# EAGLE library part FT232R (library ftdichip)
Source: http://www.ftdichip.com/Documents/DataSheets/DS_FT232R_v104.pdf
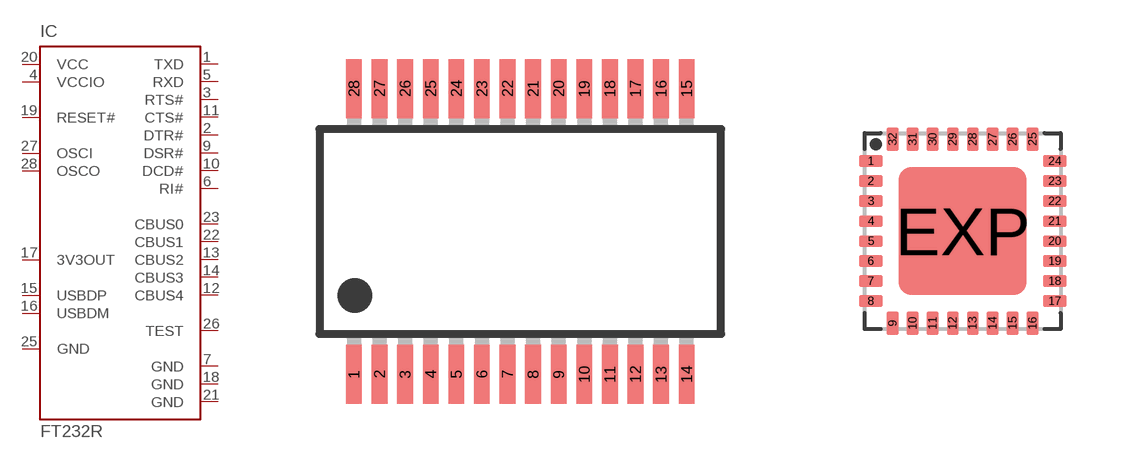
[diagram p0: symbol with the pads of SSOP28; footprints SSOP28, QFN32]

Designator prefix IC

## FT232RL  [SSOP28]
1  TXD  in
2  DTR#  in
3  RTS#  in
4  VCCIO  in
5  RXD  in
6  RI#  in
7  GND  in
9  DSR#  in
10  DCD#  in
11  CTS#  in
12  CBUS4  in
13  CBUS2  in
14  CBUS3  in
15  USBDP  in
16  USBDM  in
17  3V3OUT  in
18  GND  in
19  RESET#  in
20  VCC  in
21  GND  in
22  CBUS1  in
23  CBUS0  in
25  GND  in
26  TEST  in
27  OSCI  in
28  OSCO  in

## FT232RQ  [QFN32]
1  VCCIO  in
2  RXD  in
3  RI#  in
4  GND  in
6  DSR#  in
7  DCD#  in
8  CTS#  in
9  CBUS4  in
10  CBUS2  in
11  CBUS3  in
14  USBDP  in
15  USBDM  in
16  3V3OUT  in
17  GND  in
18  RESET#  in
19  VCC  in
20  GND  in
21  CBUS1  in
22  CBUS0  in
24  GND  in
26  TEST  in
27  OSCI  in
28  OSCO  in
30  TXD  in
31  DTR#  in
32  RTS#  in

## Footprint SSOP28 (pad centres in mm)
Shrink Small Outline Package SSOP-28 http://www.ftdichip.com/Documents/DataSheets/DS_FT232R_v104.pdf
smd 0.4 x 1.5: 1 -4.225,-3.625; 2 -3.575,-3.625; 3 -2.925,-3.625; 4 -2.275,-3.625; 5 -1.625,-3.625; 6 -0.975,-3.625; 7 -0.325,-3.625; 8 0.325,-3.625; 9 0.975,-3.625; 10 1.625,-3.625; 11 2.275,-3.625; 12 2.925,-3.625; 13 3.575,-3.625; 14 4.225,-3.625; 15 4.225,3.625; 16 3.575,3.625; 17 2.925,3.625; 18 2.275,3.625; 19 1.625,3.625; 20 0.975,3.625; 21 0.325,3.625; 22 -0.325,3.625; 23 -0.975,3.625; 24 -1.625,3.625; 25 -2.275,3.625; 26 -2.925,3.625; 27 -3.575,3.625; 28 -4.225,3.625

## Footprint QFN32 (pad centres in mm)
QFN 32 Source: http://www.ftdichip.com/Documents/DataSheets/DS_FT232R_v104.pdf
smd 0.6 x 0.3: 1 -2.3,1.75; 2 -2.3,1.25; 3 -2.3,0.75; 4 -2.3,0.25; 5 -2.3,-0.25; 6 -2.3,-0.75; 7 -2.3,-1.25; 8 -2.3,-1.75; 17 2.3,-1.75; 18 2.3,-1.25; 19 2.3,-0.75; 20 2.3,-0.25; 21 2.3,0.25; 22 2.3,0.75; 23 2.3,1.25; 24 2.3,1.75
smd 0.3 x 0.6: 9 -1.75,-2.3; 10 -1.25,-2.3; 11 -0.75,-2.3; 12 -0.25,-2.3; 13 0.25,-2.3; 14 0.75,-2.3; 15 1.25,-2.3; 16 1.75,-2.3; 25 1.75,2.3; 26 1.25,2.3; 27 0.75,2.3; 28 0.25,2.3; 29 -0.25,2.3; 30 -0.75,2.3; 31 -1.25,2.3; 32 -1.75,2.3
smd 3.2 x 3.2: EXP 0,0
